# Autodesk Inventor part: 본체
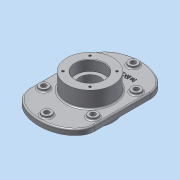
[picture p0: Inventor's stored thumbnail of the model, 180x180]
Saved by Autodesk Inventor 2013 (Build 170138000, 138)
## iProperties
Created: 2015-02
Part Number: 본체
Material: 알루미늄 6061
Document SubType Name: Modeling
Designer: Administrator
Density: 2.71 g/cm^3
Mass: 1661.12 g
Surface Area: 923.315 cm^2
Volume: 612.961 cm^3
Author: Administrator
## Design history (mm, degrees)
sketch "스케치2"
  geometry: L1 (0, 110)-(0, -110); L2 (-70, 0)-(70, 0); L3 (-70, 60)-(70, 60); L4 (-70, -60)-(70, -60); L5 (-70, 60)-(-70, -60); L6 (70, 60)-(70, -60); 4 further points; 2 other entities
  constraints: 12 end point, 8 vertical, 4 midpoint, 2 parallel, 1 coincident, 1 perpendicular, 10 other
  dimensions: "d1" = 220 distance of L1.start L1.end; "d2" = 140 distance of L2.start L2.end; "d3" = 60 distance between parallel lines of L2 L3; "d4" = 60 distance between parallel lines of L4 L2
extrude "돌출1" new body sketch "스케치2" distance "d5" = 6; taper "d7" = 0 deg; dims "d6" = 6, "d8" = 0
sketch "스케치3"
  geometry: C1 r 50 at (0, 0); 1 further point
  constraints: 1 centre point, 1 coincident
  dimensions: "d9" = 100 diameter of C1
extrude "돌출2" join sketch "스케치3" distance "d10" = 35; taper "d11" = 0 deg
sketch "스케치4"
  geometry: C1 r 50 at (0, 0); 1 further point
  constraints: 1 centre point, 1 coincident
  dimensions: "d12" = 100 diameter of C1
extrude "돌출3" join sketch "스케치4" distance "d13" = 23; taper "d14" = 0 deg
hole "구멍1" diameter "d17" = 45; stored, may be unused: countersink angle "d21" = 90 deg, drill point angle "d23" = 0 deg; dims "d18" = 6, "d19" = 62, "d20" = 22, "d22" = 35, "d24" = 10, "d25" = 10
hole "구멍2" diameter "d28" = 45; stored, may be unused: countersink angle "d32" = 90 deg, drill point angle "d34" = 0 deg; dims "d26" = 10, "d27" = 10, "d29" = 6, "d30" = 62, "d31" = 22, "d33" = 35
sketch "스케치5"
  geometry: L1 (0, 0)-(0, 41); L2 (0, 0)-(-28.991, 28.991); A1 r 41 centre (0, 0) between (0, 41) and (-28.991, 28.991); 5 further points
  constraints: 4 end point, 2 coincident, 2 point on circle, 1 centre point, 1 vertical, 5 other
  dimensions: "d35" = 82 diameter of A1; "d36" = 45 deg angle of L2 L1; "d40" = 360 deg dimension on point (0, 0) point (-28.991, 28.991) (derived)
hole "구멍3" sketch "스케치5" at (-28.991, 28.991), (-28.991, -28.991), (28.991, -28.991), (28.991, 28.991) diameter "d42" = 4.917; stored, may be unused: countersink angle "d46" = 90 deg, drill point angle "d48" = 118 deg; dims "d43" = 10, "d44" = 62, "d45" = 22, "d47" = 13
node "작업 평면1"
sketch "스케치6"
  geometry: 2 further points
  constraints: 1 vertical alignment, 1 other
  dimensions: "d49" = 65 distance of point (0, 0) point (0, 65)
feature "엠보싱1" sketch "스케치6" dims "d1" = 220, "d2" = 140, "d3" = 60, "d4" = 60, "d24" = 10, "d50" = 1, "d51" = 0
sketch "스케치7"
  geometry: L1 (70, -60)-(70, 60) reference; L2 (-70, 60)-(-70, -60) reference; L3 (24.022, 65.353)-(24.022, 63.258) reference; L4 (28.798, 63.583)-(28.874, 62.986) reference; L5 (23.305, 62.617)-(23.305, 68.425) reference; L6 (23.305, 68.425)-(27.94, 68.425) reference; L7 (27.94, 68.425)-(27.94, 67.828) reference; L8 (27.94, 67.828)-(24.022, 67.828) reference; L9 (24.022, 67.828)-(24.022, 65.95) reference; L10 (24.022, 65.95)-(27.517, 65.95) reference; L11 (27.517, 65.95)-(27.517, 65.353) reference; L12 (27.517, 65.353)-(24.022, 65.353) reference; L13 (19.919, 69.336)-(19.919, 62.335) reference; L14 (19.919, 62.335)-(19.191, 62.335) reference; L15 (19.191, 62.335)-(19.191, 69.673) reference; L16 (19.191, 69.673)-(19.767, 69.673) reference; L17 (18.062, 69.174)-(18.062, 62.737) reference; L18 (18.062, 62.737)-(17.335, 62.737) reference; L19 (17.335, 62.737)-(17.335, 66.612) reference; L20 (17.335, 66.612)-(15.685, 66.612) reference; L21 (15.685, 66.612)-(15.685, 67.166) reference; L22 (15.685, 67.166)-(17.335, 67.166) reference; L23 (17.335, 67.166)-(17.335, 69.554) reference; L24 (17.335, 69.554)-(17.932, 69.554) reference; L25 (20.147, 60.794)-(20.147, 60.197) reference; L26 (20.147, 60.197)-(13.232, 60.197) reference; L27 (13.232, 60.197)-(13.232, 63.258) reference; L28 (13.232, 63.258)-(13.764, 63.258) reference; L29 (13.948, 62.932)-(13.948, 60.794) reference; L30 (13.948, 60.794)-(20.147, 60.794) reference; L31 (16.662, 64.604)-(16.174, 64.05) reference; L32 (11.864, 63.725)-(11.365, 64.267) reference; L33 (13.872, 69.25)-(14.513, 69.25) reference; L34 (9.65, 63.431)-(10.366, 63.431) reference; L35 (10.301, 66.482)-(9.574, 66.482) reference; L36 (2.442, 68.815)-(2.442, 68.153) reference; L37 (2.442, 68.153)-(-0.054, 68.153) reference; L38 (-0.054, 68.153)-(-0.054, 60.815) reference; L39 (-0.054, 60.815)-(-0.782, 60.815) reference; L40 (-0.782, 60.815)-(-0.782, 68.153) reference; L41 (-0.782, 68.153)-(-3.267, 68.153) reference; L42 (-3.267, 68.153)-(-3.267, 68.815) reference; L43 (-3.267, 68.815)-(2.442, 68.815) reference; L44 (-16.152, 63.638)-(-13.254, 63.638) reference; L45 (-13.254, 63.638)-(-13.254, 60.24) reference; L46 (-13.254, 60.24)-(-13.992, 60.24) reference; L47 (-13.992, 60.24)-(-13.992, 63.041) reference; L48 (-13.992, 63.041)-(-20.125, 63.041) reference; L49 (-20.125, 63.041)-(-20.125, 63.638) reference; L50 (-20.125, 63.638)-(-16.879, 63.638) reference; L51 (-16.879, 63.638)-(-16.879, 65.592) reference; L52 (-16.879, 65.592)-(-21.297, 65.592) reference; L53 (-21.297, 65.592)-(-21.297, 66.189) reference; L54 (-21.297, 66.189)-(-14.307, 66.189) reference; L55 (-13.851, 68.859)-(-19.94, 68.859) reference; L56 (-19.94, 68.859)-(-19.94, 69.467) reference; L57 (-19.94, 69.467)-(-13.08, 69.467) reference; L58 (-13.514, 66.189)-(-11.691, 66.189) reference; L59 (-11.691, 66.189)-(-11.691, 65.592) reference; L60 (-11.691, 65.592)-(-16.152, 65.592) reference; L61 (-16.152, 65.592)-(-16.152, 63.638) reference; L62 (-4.668, 60.815)-(-5.558, 63.258) reference; L63 (-5.558, 63.258)-(-9.161, 63.258) reference; L64 (-9.161, 63.258)-(-10.073, 60.815) reference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; C1 r 50 at (0, 0) reference; 64 further points; 2 other entities
  constraints: 8 end point, 8 point on line, 4 parallel, 2 coincident, 1 horizontal alignment, 1 perpendicular, 1 vertical alignment, 83 other
  dimensions: "d52" = 17 distance between parallel lines of L1 L100; "d56" = 360 deg dimension on point (0, 0) point (0, 93) (derived)
hole "구멍4" sketch "스케치7" at (0, 93), (-80.54, 46.5), (-80.54, -46.5), (0, -93), (80.54, -46.5), (80.54, 46.5), (-53, 46.5), (53, 46.5), (53, -46.5), (-53, -46.5) diameter "d58" = 11; stored, may be unused: countersink angle "d62" = 90 deg, drill point angle "d64" = 118 deg; dims "d59" = 11, "d60" = 62, "d61" = 22, "d63" = 13
sketch "스케치8"
  geometry: L1 (70, 60)-(70, -60) reference; L2 (-70, -60)-(-70, 60) reference; C1 r 5.5 at (0, 93) reference; C2 r 5.5 at (-53, 46.5) reference; C3 r 5.5 at (53, 46.5) reference; C4 r 5.5 at (53, -46.5) reference; C5 r 5.5 at (-53, -46.5) reference; C6 r 10 at (0, 93); C7 r 5.5 at (53, -46.5) reference; C8 r 5.5 at (-53, 46.5) reference; C9 r 5.5 at (0, 93) reference; C10 r 5.5 at (0, -93) reference; C11 r 5.5 at (53, 46.5) reference; C12 r 5.5 at (-53, -46.5) reference; C13 r 50 at (0, 0) reference; C14 r 10 at (-53, 46.5); C15 r 10 at (-53, -46.5); C16 r 10 at (0, -93); C17 r 10 at (53, -46.5); C18 r 10 at (53, 46.5); 3 further points; 2 other entities
  constraints: 6 centre point, 6 coincident, 2 other
  dimensions: "d65" = 20 diameter of C6; "d66" = 20 diameter of C14; "d67" = 20 diameter of C15; "d68" = 20 diameter of C16; "d69" = 20 diameter of C17; "d70" = 20 diameter of C18
extrude "돌출4" join sketch "스케치8" distance "d71" = 5; taper "d72" = 0 deg
fillet "모깎기1" dims "d73" = 3
fillet "모깎기2" dims "d74" = 0.3
chamfer "모따기1" distance "d75" = 1; stored, may be unused: second distance "d76" = 2, angle "d77" = 45 deg
node "솔리드1"
mirror "대칭1"
node "투영된 루프1"
node "투영된 루프2"
